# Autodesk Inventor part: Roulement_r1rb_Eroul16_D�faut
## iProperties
Created: 2011-01
Part Number: Roulement_r1rb_Eroul16_D�faut
Document SubType Name: Modeling
Designer: eric
Density: 1 g/cm^3
Mass: 0.0387924 g
Surface Area: 0.554177 cm^2
Volume: 0.0387924 cm^3
Author: eric
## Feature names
1. Base1
